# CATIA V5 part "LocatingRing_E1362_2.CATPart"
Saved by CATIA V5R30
Part number: Stredici_krouzek_vstrikovaci
Nomenclature: E1362/125/90/36X20
Description: MEUSBURGER
Property "Material": "1.0503"
Publications: "DrillHole", "Base", "TapHole"
Bounding box of the stored display mesh (mm): x -62.5 to 62.5, y -62.5 to 62.5, z -8 to 12
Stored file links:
  E:\Bakalarka\Model\Forma_v7\LocatingRing_E1362_2.CATPart
  E:\dev\MoldDesign\intel_a\startup\components\MoldCatalog\LocatingRing\Meusburger\LocatingRing_E1362\TableE1362.txt
  E:\Bakalarka\Model\Forma_v7\Vstrikovaci_cast.CATProduct
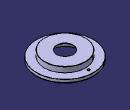
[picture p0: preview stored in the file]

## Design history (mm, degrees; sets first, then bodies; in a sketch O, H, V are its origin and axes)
Parameters
  Ref = "E1362/125/90/36X20" {design table}
  ShD = 125 mm {design table}
  L = 20 mm {design table}
  L3 = 8 mm {design table}
  D1 = 90 mm {design table}
  D2 = 36 mm {design table}
  D3 = 125 mm {design table}
  L4 = 2 mm {design table}
  L2 = 1 mm {design table}
  F = 0.5 mm {design table}
  F1 = 0.3 mm {design table}
  W = 45 deg {design table}
  W1 = 30 deg {design table}
  L1 = 11.8 mm {design table}
  D4 = 104 mm {design table}
  M = 5 mm {design table}
  D5 = 5.5 mm {design table}
  D6 = 9.5 mm {design table}
  T6 = 6 mm {design table}
  k_l5 = 12 mm {design table}
  k_dkern = 4.13 mm {design table}
  k_lkern = 14 mm {design table}
  Version = 2 {design table}
  Pitch = 0.8 mm {design table}
  Mat = "1.0503" {design table}
  HeatTreat = "" {design table}
  SupplierRef = "Meusburger 2017"
  BmpRef = "F_MldLocatingRing_D1_D3_L"
  DrillHole_Length = 225 mm
  D = 90 mm {= D1}
Set1 "BaseBody"
  Point1 "Base": (0, 0, 0)
  Plane1: type Offset, RefPlane xy-plane, Offset 225 {= DrillHole_Length}, reversed
  Plane2: type Offset, RefPlane xy-plane, Offset -8
  Plane3: type Offset, RefPlane xy-plane, Offset 8 {= L3}, reversed
Body1 (main body)
  Sketch1 "Sketch.1" on yz-plane, origin (0, 0, 0), H (0, 1, 0), V (0, 0, 1)
    line L1 (37, -8) -> (62.5, -8)
    line L2 (62.5, -8) -> (62.5, 0)
    line L3 (62.5, 0) -> (45, 0)
    line L4 (45, 0) -> (45, 12)
    axis line L5 (0, -8) -> (0, 12)
    point P6 (0, -8)
    point P7 (0, 12)
    line L6 (37, -8) -> (18, 11)
    point P8 (18, 11)
    line L7 (18, 11) -> (18, 12)
    line L8 (18, 12) -> (45, 12)
    distance L3 L1 = 8 {= L3}
    distance L4 L5 = 45 {= D1 /2}
    distance L2 L5 = 62.5 {= D3/2}
    distance P8 L8 = 1 {= L2}
    distance L7 L5 = 18 {= D2 /2}
    distance L1 L8 = 20 {= L}
    angle L6 L1 = 45 {= W}
    horizontal: L1 H, L3 H, L8 H
    vertical: L2 V, L4 V, L7 V
    coincidence: P6 V, L5 V, L3 H, P6 L1, P7 L8
  Shaft1: profile Sketch1, axis Sketch1.L5, angle 360
  Sketch2 "Sketch.2" on Plane2, origin (-12.4424, -33.1984, -8), H (1, 0, 0), V (0, -1, 0)
    point P1 (12.4424, -85.1984)
    construction circle A1 centre (12.4424, -33.1984) radius 52
    reference projected point E1 (12.4424, -33.1984) from Point1
    reference intersected line E2 through (12.4424, 0) direction (0, 1) from yz-plane
    radius A1 = 52 {= D4 /2}
    coincidence: P1 A1, E2 P1
    concentricity: A1 E1
  Hole1 "Hole.1": placed by Sketch2, at (0, 52, -8) direction (0, 0, 1), diameter 5.5 {= D5}, through (limit type 3), counterbore diameter 9.5 {= D6}, counterbore depth 6 {= T6}
  Mirror1: of Hole1, about zx-plane
  Chamfer1: length 2 {= L4}, angle 30 {= W1}, on edge [face of Shaft1 from Sketch1.L1 | face of Shaft1 from Sketch1.L2]
  Chamfer2: length 0.3 {= F1}, second length 0.3 {= F1}, on edge [face of Shaft1 from Sketch1.L2 | face of Shaft1 from Sketch1.L3]
  Chamfer3: length 0.5 {= F}, second length 0.5 {= F}, on edge [face of Shaft1 from Sketch1.L4 | face of Shaft1 from Sketch1.L8]
  Chamfer4: length 0.3 {= F1}, angle 45, on edge [face of Shaft1 from Sketch1.L3 | face of Shaft1 from Sketch1.L4], deactivated
  Body2 "Result of DrillHole"
    Solid1: linked copy from another document
  Assemble1 "DrillHoleCapScrew_E1200_5.1": tool Body2
  Body3 "Result of DrillHole"
    Solid2: linked copy from another document
  Assemble2 "DrillHoleCapScrew_E1200_5.2": tool Body3
  Sketch3 on face of Shaft1 from Sketch1.L1, origin (0, 0, -8), H (1, 0, 0), V (0, -1, 0)
    reference projected circle E1 centre (0, -52) radius 4.75 from edge [face of Hole1 | face of Shaft1 from Sketch1.L1]
    reference projected circle E2 centre (0, 52) radius 4.75 from edge [face of Mirror1 | face of Shaft1 from Sketch1.L1]
    point P1 (0, 52)
    point P2 (0, -52)
    concentricity: P1 E2, P2 E1
Body4 "DrillHole"
  Sketch4 "Sketch.3" on Plane1, origin (0, 0, -225), H (1, 0, 0), V (0, 1, 0)
    point P1 (0, 0)
    reference projected point E1 (0, 0) from Point1
    coincidence: E1 P1
  Hole2: placed by Sketch4, at (0, 0, -225) direction (0, 0, 1), diameter 90 {= D1}, depth 237 {= Plane1.Offset +k_l5}
Body5 "TapHole"
  Sketch5 "Sketch.4" on xy-plane, origin (-10.7066, 10.7066, 0), H (1, 0, 0), V (0, 1, 0)
    point P1 (10.7066, -62.7066)
    construction circle A1 centre (10.7066, -10.7066) radius 52
    reference projected circle E1 centre (10.7066, -10.7066) radius 45 from edge [face of Hole2 | face of Hole2]
    reference intersected line E2 through (10.7066, 0) direction (0, 1) from yz-plane
    radius A1 = 52 {= D4/2}
    concentricity: E1 A1
    coincidence: P1 A1, P1 E2
  Hole3 "Hole.3": placed by Sketch5, at (0, -52, 0) direction (0, 0, 1), diameter 4.13 {= k_dkern}, depth 14 {= Hole3.ThreadingDepth}, V-bottom angle 120, threaded, thread diameter 5 {= M}, thread depth 14, pitch 0.8 {= Pitch}
  Mirror2: of Hole3, about zx-plane
Relations
  design table "TableE1362", configuration 31, drives Ref, ShD, L, L3, D1, D2, D3, L4, L2, F, F1, W, W1, L1, D4, M, D5, D6, T6, k_l5, k_dkern, k_lkern, Version, Pitch, Mat, HeatTreat
  rule "D1-D3_definition":
    if D3 >D1
    {
    	Chamfer2.Activity = true
    	Chamfer4.Activity = false
    }
    if D1>D3
    {
    	Chamfer2.Activity = false
    	Chamfer4.Activity = true
    }
    if D1==D3
    {
    	Chamfer2.Activity = false
    	Chamfer4.Activity = false
    }
  rule "Holes_Position":
    if D4 >ShD
    	Plane2.Offset =0mm
    if D4<ShD or ShD==D1
    	Plane2.Offset =-L3
  rule "Taphole_Activity":
    If Version == 1
    {
    	Hole3.ThreadingDepth = (L-L3) + k_lkern
    }
    If Version == 2
    {
    	Hole3.ThreadingDepth = k_lkern
    }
